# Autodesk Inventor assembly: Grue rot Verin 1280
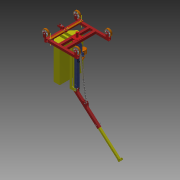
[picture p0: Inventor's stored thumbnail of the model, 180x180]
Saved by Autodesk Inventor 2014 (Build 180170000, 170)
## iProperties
Created: 2015-07
Part Number: Grue rot Verin 1280
Document SubType Name: Assembly
Designer: OL
Author: OL
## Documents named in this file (29)
- D:\Lycée Larmand\Profs\SUJET BAC EDPI ETC\ELABORATION SUJET EDPI\Bourgeois RT 510\Modele Grue rotative\Grue rot Verin 1280.iam
- D:\Lycée Larmand\Profs\SUJET BAC EDPI ETC\ELABORATION SUJET EDPI\Bourgeois RT 510\Modele Grue rotative\Cadre chariot.ipt
- D:\Lycée Larmand\Profs\SUJET BAC EDPI ETC\ELABORATION SUJET EDPI\Bourgeois RT 510\Modele Grue rotative\Axe.ipt
- D:\Lycée Larmand\Profs\SUJET BAC EDPI ETC\ELABORATION SUJET EDPI\Bourgeois RT 510\Modele Grue rotative\Poteau central.ipt
- D:\Lycée Larmand\Profs\SUJET BAC EDPI ETC\ELABORATION SUJET EDPI\Bourgeois RT 510\Modele Grue rotative\Potence pivot.ipt
- D:\Lycée Larmand\Profs\SUJET BAC EDPI ETC\ELABORATION SUJET EDPI\Bourgeois RT 510\Modele Grue rotative\Potence coulissante.ipt
- D:\Lycée Larmand\Profs\SUJET BAC EDPI ETC\ELABORATION SUJET EDPI\Bourgeois RT 510\Modele Grue rotative\Contrepoids.ipt
- D:\Lycée Larmand\Profs\SUJET BAC EDPI ETC\ELABORATION SUJET EDPI\Bourgeois RT 510\Modele Grue rotative\pompe\Pompe.ipt
- D:\Lycée Larmand\Profs\SUJET BAC EDPI ETC\ELABORATION SUJET EDPI\Bourgeois RT 510\Modele Grue rotative\Verin630-5-corps.ipt
- D:\Lycée Larmand\Profs\SUJET BAC EDPI ETC\ELABORATION SUJET EDPI\Bourgeois RT 510\Modele Grue rotative\Verin630-5-tige.ipt
- D:\Lycée Larmand\Profs\SUJET BAC EDPI ETC\ELABORATION SUJET EDPI\Bourgeois RT 510\Modele Grue rotative\Roue.ipt
- D:\Lycée Larmand\Profs\SUJET BAC EDPI ETC\ELABORATION SUJET EDPI\Bourgeois RT 510\Modele Grue rotative\Pivot de Direction.ipt
- D:\Lycée Larmand\Profs\SUJET BAC EDPI ETC\ELABORATION SUJET EDPI\Bourgeois RT 510\Modele Grue rotative\Palier de roue.ipt
- D:\Lycée Larmand\Profs\SUJET BAC EDPI ETC\ELABORATION SUJET EDPI\Bourgeois RT 510\Modele Grue rotative\Biellette.ipt
- D:\Lycée Larmand\Profs\SUJET BAC EDPI ETC\ELABORATION SUJET EDPI\Bourgeois RT 510\Modele Grue rotative\Vis H M10x20_02.ipt
- D:\Lycée Larmand\Profs\SUJET BAC EDPI ETC\ELABORATION SUJET EDPI\Bourgeois RT 510\Modele Grue rotative\Ecrou H M10x20_01.ipt
- D:\Lycée Larmand\Profs\SUJET BAC EDPI ETC\ELABORATION SUJET EDPI\Bourgeois RT 510\Modele Grue rotative\Axe D20.ipt
- D:\Lycée Larmand\Profs\SUJET BAC EDPI ETC\ELABORATION SUJET EDPI\Bourgeois RT 510\Modele Grue rotative\Goupille D20.ipt
- D:\Lycée Larmand\Profs\SUJET BAC EDPI ETC\ELABORATION SUJET EDPI\Bourgeois RT 510\Modele Grue rotative\Axe D20 L122.ipt
- D:\Lycée Larmand\Profs\SUJET BAC EDPI ETC\ELABORATION SUJET EDPI\Bourgeois RT 510\Modele Grue rotative\Rondelle d'appui D20.ipt
- D:\Lycée Larmand\Profs\SUJET BAC EDPI ETC\ELABORATION SUJET EDPI\Bourgeois RT 510\Modele Grue rotative\Axe D20 L96.ipt
- D:\Lycée Larmand\Profs\SUJET BAC EDPI ETC\ELABORATION SUJET EDPI\Bourgeois RT 510\Modele Grue rotative\Axe Roue D25 L116.ipt
- D:\Lycée Larmand\Profs\SUJET BAC EDPI ETC\ELABORATION SUJET EDPI\Bourgeois RT 510\Modele Grue rotative\Rondelle d'appui D25.ipt
- D:\Lycée Larmand\Profs\SUJET BAC EDPI ETC\ELABORATION SUJET EDPI\Bourgeois RT 510\Modele Grue rotative\Goupille D25.ipt
- D:\Lycée Larmand\Profs\SUJET BAC EDPI ETC\ELABORATION SUJET EDPI\Bourgeois RT 510\Modele Grue rotative\Butée manuelle.ipt
- D:\Lycée Larmand\Profs\SUJET BAC EDPI ETC\ELABORATION SUJET EDPI\Bourgeois RT 510\Modele Grue rotative\Goupille Cavalier.ipt
- D:\Lycée Larmand\Profs\SUJET BAC EDPI ETC\ELABORATION SUJET EDPI\Bourgeois RT 510\Modele Grue rotative\Bague d'arrêt D25.ipt
- D:\Lycée Larmand\Profs\SUJET BAC EDPI ETC\ELABORATION SUJET EDPI\Bourgeois RT 510\Modele Grue rotative\tuyau 1.ipt
- D:\Lycée Larmand\Profs\SUJET BAC EDPI ETC\ELABORATION SUJET EDPI\Bourgeois RT 510\Modele Grue rotative\tuyau 2.ipt
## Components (72 placed, 28 different names)
1. Cadre chariot:1 — Logement:1, Logement:9, Logement:10, Logement:12, Logement:13, Angle:1, Logement:37, Angle:12, Logement:38, Logement:39, Logement:42, Angle:15, Logement:43, Logement:44, Angle:16, Angle:17, Logement:54, Logement:74, Logement:75
2. Axe:1 — Logement:1, Logement:2
3. Poteau central:1 — Logement:2, Logement:3, Logement:4, Placage:3, Logement:5, Logement:6, Logement:7, Logement:21, Logement:22, Angle:3, Angle:6, Angle:7, Logement:27, Logement:28, Logement:57, Angle:20, Angle:22, Logement:58, Logement:60, Angle:24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
4. Potence pivot:1 — Logement:3, Placage:1, Placage:2, Placage:11, Logement:32, Angle:9, Logement:33, Logement:34, Logement:62, Angle:28
5. Potence coulissante:1 — Placage:1, Placage:2, Tangente:3
6. Contrepoids:1 — Logement:4, Placage:3, Angle:1, Angle:2, Logement:25, Logement:30, Logement:31
7. Pompe:1 — Logement:5, Logement:6, Logement:20, Logement:56, Angle:21, Angle:23, Logement:59, Logement:61, Angle:26, Angle:27, Logement:72
8. Verin630-5-corps:1 — Logement:7, Placage:4, Logement:73
9. Verin630-5-tige:1 — Placage:4, Placage:10
10. Roue:1 — Logement:9
11. Roue:2 — Logement:10
12. Pivot de Direction:1 — Logement:54, Logement:63, Angle:30, Angle:31, Placage:19, Placage:20
13. Palier de roue:1 — Logement:12, Logement:17, Logement:18, Placage:6, Angle:19, Logement:49, Logement:50, Logement:53, Placage:17, Angle:33
14. Palier de roue:2 — Logement:13, Logement:19, Angle:2, Placage:5, Logement:47, Angle:18, Logement:51, Logement:52, Logement:55, Placage:18, Angle:32
15. Biellette:1 — Logement:17, Placage:14, Logement:64, Logement:70
16. Biellette:2 — Logement:55, Placage:13, Logement:65, Logement:68
17. Roue:3 — Logement:18
18. Roue:4 — Logement:19
19. Vis H M10x20_02:1 — Logement:20, Angle:23
20. Ecrou H M10x20_01:1 — Logement:21, Angle:22
21. Axe D20:1 — Logement:22, Angle:3, Logement:23, Angle:4, Logement:24, Angle:5, Placage:24
22. Goupille D20:1 — Logement:24, Angle:5
23. Goupille D20:2 — Logement:23, Angle:4
24. Goupille D20:3 — Logement:26, Angle:7
25. Goupille D20:4 — Logement:29, Angle:8
26. Axe D20 L122:1 — Logement:25, Logement:26, Angle:6, Logement:29, Angle:8
27. Rondelle d'appui D20:1 — Logement:27
28. Rondelle d'appui D20:2 — Logement:28
29. Rondelle d'appui D20:3 — Logement:30
30. Rondelle d'appui D20:4 — Logement:31
31. Axe D20 L96:1 — Logement:32, Angle:9, Logement:35, Angle:10, Logement:36, Angle:11, Placage:23
32. Rondelle d'appui D20:5 — Logement:34
33. Rondelle d'appui D20:6 — Logement:33
34. Goupille D20:5 — Logement:35, Angle:10
35. Goupille D20:6 — Logement:36, Angle:11
36. Axe Roue D25 L116:1 — Logement:37, Angle:12, Angle:13, Angle:14
37. Rondelle d'appui D25:1 — Logement:38, Logement:41
38. Rondelle d'appui D25:2 — Logement:39, Logement:40
39. Goupille D25:1 — Logement:41, Angle:14
40. Goupille D25:2 — Logement:40, Angle:13
41. Axe Roue D25 L116:2 — Logement:42, Angle:15
42. Rondelle d'appui D25:3 — Logement:44, Logement:45
43. Rondelle d'appui D25:4 — Logement:43, Logement:46
44. Goupille D25:3 — Logement:45, Angle:16
45. Goupille D25:4 — Logement:46, Angle:17
46. Axe Roue D25 L116:3 — Logement:47, Angle:18
47. Axe Roue D25 L116:4 — Angle:19, Logement:53
48. Rondelle d'appui D25:5 — Logement:49
49. Rondelle d'appui D25:6 — Logement:50
50. Rondelle d'appui D25:7 — Logement:52
51. Rondelle d'appui D25:8 — Logement:51
52. Vis H M10x20_02:2 — Logement:56, Angle:21
53. Ecrou H M10x20_01:2 — Logement:57, Angle:20
54. Vis H M10x20_02:3 — Logement:59, Angle:26
55. Ecrou H M10x20_01:3 — Logement:58, Angle:24
56. Vis H M10x20_02:4 — Logement:61, Angle:27
57. Ecrou H M10x20_01:4 — Logement:60, Angle:25
58. Butée manuelle:1 — Logement:62, Angle:28, Placage:15, Affleurement:1, Angle:29, Tangente:3
59. Goupille Cavalier:1 — Placage:16, Affleurement:1, Angle:29
60. Bague d'arrêt D25:1 — Logement:63
61. Rondelle d'appui D20:7 — Logement:65, Logement:66, Placage:22
62. Rondelle d'appui D20:8 — Logement:64, Logement:67
63. Goupille D20:7 — Logement:66, Angle:30
64. Goupille D20:8 — Logement:67, Angle:31
65. Goupille D20:9 — Logement:69, Angle:32
66. Rondelle d'appui D20:9 — Logement:68, Logement:69
67. Rondelle d'appui D20:10 — Logement:70, Logement:71
68. Goupille D20:10 — Logement:71, Angle:33
69. tuyau 1:1 — Logement:72, Tangente:2
70. tuyau 2:1 — Logement:73, Tangente:2
71. Bague d'arrêt D25:2 — Logement:74
72. Bague d'arrêt D25:3 — Logement:75
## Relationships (124: Insert 69, Angle 33, Mate 19, Tangent 2, Flush 1)
- Logement:1 [Insert]: Cadre chariot:1 ↔ Axe:1
- Logement:2 [Insert]: Axe:1 ↔ Poteau central:1
- Logement:3 [Insert]: Poteau central:1 ↔ Potence pivot:1
- Placage:1 [Mate]: Potence pivot:1 ↔ Potence coulissante:1
- Placage:2 [Mate]: Potence pivot:1 ↔ Potence coulissante:1
- Logement:4 [Insert]: Poteau central:1 ↔ Contrepoids:1
- Placage:3 [Mate]: Poteau central:1 ↔ Contrepoids:1
- Logement:5 [Insert]: Poteau central:1 ↔ Pompe:1
- Logement:6 [Insert]: Poteau central:1 ↔ Pompe:1
- Logement:7 [Insert]: Poteau central:1 ↔ Verin630-5-corps:1
- Placage:4 [Mate]: Verin630-5-corps:1 ↔ Verin630-5-tige:1
- Logement:9 [Insert]: Cadre chariot:1 ↔ Roue:1
- Logement:10 [Insert]: Cadre chariot:1 ↔ Roue:2
- Logement:12 [Insert]: Cadre chariot:1 ↔ Palier de roue:1
- Logement:13 [Insert]: Cadre chariot:1 ↔ Palier de roue:2
- Logement:17 [Insert]: Palier de roue:1 ↔ Biellette:1
- Logement:18 [Insert]: Palier de roue:1 ↔ Roue:3
- Logement:19 [Insert]: Palier de roue:2 ↔ Roue:4
- Angle:1: Cadre chariot:1 ↔ Contrepoids:1
- Angle:2: Contrepoids:1 ↔ Palier de roue:2
- Placage:5 [Mate]: Palier de roue:2
- Placage:6 [Mate]: Palier de roue:1
- Logement:20 [Insert]: Pompe:1 ↔ Vis H M10x20_02:1
- Logement:21 [Insert]: Poteau central:1 ↔ Ecrou H M10x20_01:1
- Logement:22 [Insert]: Poteau central:1 ↔ Axe D20:1
- Angle:3: Poteau central:1 ↔ Axe D20:1
- Logement:23 [Insert]: Axe D20:1 ↔ Goupille D20:2
- Angle:4: Axe D20:1 ↔ Goupille D20:2
- Logement:24 [Insert]: Axe D20:1 ↔ Goupille D20:1
- Angle:5: Axe D20:1 ↔ Goupille D20:1
- Placage:10 [Mate]: Verin630-5-tige:1
- Placage:11 [Mate]: Potence pivot:1
- Logement:25 [Insert]: Contrepoids:1 ↔ Axe D20 L122:1
- Logement:26 [Insert]: Goupille D20:3 ↔ Axe D20 L122:1
- Angle:6: Poteau central:1 ↔ Axe D20 L122:1
- Angle:7: Poteau central:1 ↔ Goupille D20:3
- Logement:27 [Insert]: Poteau central:1 ↔ Rondelle d'appui D20:1
- Logement:28 [Insert]: Poteau central:1 ↔ Rondelle d'appui D20:2
- Logement:29 [Insert]: Goupille D20:4 ↔ Axe D20 L122:1
- Angle:8: Goupille D20:4 ↔ Axe D20 L122:1
- Logement:30 [Insert]: Contrepoids:1 ↔ Rondelle d'appui D20:3
- Logement:31 [Insert]: Contrepoids:1 ↔ Rondelle d'appui D20:4
- Logement:32 [Insert]: Potence pivot:1 ↔ Axe D20 L96:1
- Angle:9: Potence pivot:1 ↔ Axe D20 L96:1
- Logement:33 [Insert]: Potence pivot:1 ↔ Rondelle d'appui D20:6
- Logement:34 [Insert]: Potence pivot:1 ↔ Rondelle d'appui D20:5
- Logement:35 [Insert]: Axe D20 L96:1 ↔ Goupille D20:5
- Angle:10: Axe D20 L96:1 ↔ Goupille D20:5
- Logement:36 [Insert]: Axe D20 L96:1 ↔ Goupille D20:6
- Angle:11: Axe D20 L96:1 ↔ Goupille D20:6
- Logement:37 [Insert]: Cadre chariot:1 ↔ Axe Roue D25 L116:1
- Angle:12: Cadre chariot:1 ↔ Axe Roue D25 L116:1
- Logement:38 [Insert]: Cadre chariot:1 ↔ Rondelle d'appui D25:1
- Logement:39 [Insert]: Cadre chariot:1 ↔ Rondelle d'appui D25:2
- Logement:40 [Insert]: Rondelle d'appui D25:2 ↔ Goupille D25:2
- Angle:13: Axe Roue D25 L116:1 ↔ Goupille D25:2
- Logement:41 [Insert]: Rondelle d'appui D25:1 ↔ Goupille D25:1
- Angle:14: Axe Roue D25 L116:1 ↔ Goupille D25:1
- Logement:42 [Insert]: Cadre chariot:1 ↔ Axe Roue D25 L116:2
- Angle:15: Cadre chariot:1 ↔ Axe Roue D25 L116:2
- Logement:43 [Insert]: Cadre chariot:1 ↔ Rondelle d'appui D25:4
- Logement:44 [Insert]: Cadre chariot:1 ↔ Rondelle d'appui D25:3
- Logement:45 [Insert]: Rondelle d'appui D25:3 ↔ Goupille D25:3
- Angle:16: Cadre chariot:1 ↔ Goupille D25:3
- Logement:46 [Insert]: Rondelle d'appui D25:4 ↔ Goupille D25:4
- Angle:17: Cadre chariot:1 ↔ Goupille D25:4
- Logement:47 [Insert]: Palier de roue:2 ↔ Axe Roue D25 L116:3
- Angle:18: Palier de roue:2 ↔ Axe Roue D25 L116:3
- Angle:19: Palier de roue:1 ↔ Axe Roue D25 L116:4
- Logement:49 [Insert]: Palier de roue:1 ↔ Rondelle d'appui D25:5
- Logement:50 [Insert]: Palier de roue:1 ↔ Rondelle d'appui D25:6
- Logement:51 [Insert]: Palier de roue:2 ↔ Rondelle d'appui D25:8
- Logement:52 [Insert]: Palier de roue:2 ↔ Rondelle d'appui D25:7
- Logement:53 [Insert]: Palier de roue:1 ↔ Axe Roue D25 L116:4
- Logement:54 [Insert]: Cadre chariot:1 ↔ Pivot de Direction:1
- Logement:55 [Insert]: Palier de roue:2 ↔ Biellette:2
- Placage:13 [Mate]: Biellette:2
- Placage:14 [Mate]: Biellette:1
- Logement:56 [Insert]: Pompe:1 ↔ Vis H M10x20_02:2
- Logement:57 [Insert]: Poteau central:1 ↔ Ecrou H M10x20_01:2
- Angle:20: Poteau central:1 ↔ Ecrou H M10x20_01:2
- Angle:21: Pompe:1 ↔ Vis H M10x20_02:2
- Angle:22: Poteau central:1 ↔ Ecrou H M10x20_01:1
- Angle:23: Pompe:1 ↔ Vis H M10x20_02:1
- Logement:58 [Insert]: Poteau central:1 ↔ Ecrou H M10x20_01:3
- Logement:59 [Insert]: Pompe:1 ↔ Vis H M10x20_02:3
- Logement:60 [Insert]: Poteau central:1 ↔ Ecrou H M10x20_01:4
- Logement:61 [Insert]: Pompe:1 ↔ Vis H M10x20_02:4
- Angle:24: Poteau central:1 ↔ Ecrou H M10x20_01:3
- Angle:25: Poteau central:1 ↔ Ecrou H M10x20_01:4
- Angle:26: Pompe:1 ↔ Vis H M10x20_02:3
- Angle:27: Pompe:1 ↔ Vis H M10x20_02:4
- Logement:62 [Insert]: Potence pivot:1 ↔ Butée manuelle:1
- Angle:28: Potence pivot:1 ↔ Butée manuelle:1
- Placage:15 [Mate]: Butée manuelle:1
- Placage:16 [Mate]: Goupille Cavalier:1
- Affleurement:1 [Flush]: Butée manuelle:1 ↔ Goupille Cavalier:1
- Angle:29: Butée manuelle:1 ↔ Goupille Cavalier:1
- Logement:63 [Insert]: Pivot de Direction:1 ↔ Bague d'arrêt D25:1
- Logement:64 [Insert]: Biellette:1 ↔ Rondelle d'appui D20:8
- Logement:65 [Insert]: Biellette:2 ↔ Rondelle d'appui D20:7
- Logement:66 [Insert]: Rondelle d'appui D20:7 ↔ Goupille D20:7
- Angle:30: Pivot de Direction:1 ↔ Goupille D20:7
- Logement:67 [Insert]: Rondelle d'appui D20:8 ↔ Goupille D20:8
- Angle:31: Pivot de Direction:1 ↔ Goupille D20:8
- Placage:17 [Mate]: Palier de roue:1
- Placage:18 [Mate]: Palier de roue:2
- Placage:19 [Mate]: Pivot de Direction:1
- Placage:20 [Mate]: Pivot de Direction:1
- Placage:22 [Mate]: Rondelle d'appui D20:7
- Logement:68 [Insert]: Biellette:2 ↔ Rondelle d'appui D20:9
- Logement:69 [Insert]: Goupille D20:9 ↔ Rondelle d'appui D20:9
- Angle:32: Palier de roue:2 ↔ Goupille D20:9
- Logement:70 [Insert]: Biellette:1 ↔ Rondelle d'appui D20:10
- Logement:71 [Insert]: Rondelle d'appui D20:10 ↔ Goupille D20:10
- Angle:33: Palier de roue:1 ↔ Goupille D20:10
- Logement:72 [Insert]: Pompe:1 ↔ tuyau 1:1
- Logement:73 [Insert]: Verin630-5-corps:1 ↔ tuyau 2:1
- Tangente:2: tuyau 1:1 ↔ tuyau 2:1
- Logement:74 [Insert]: Cadre chariot:1 ↔ Bague d'arrêt D25:2
- Logement:75 [Insert]: Cadre chariot:1 ↔ Bague d'arrêt D25:3
- Placage:23 [Mate]: Axe D20 L96:1
- Placage:24 [Mate]: Axe D20:1
- Tangente:3: Potence coulissante:1 ↔ Butée manuelle:1
